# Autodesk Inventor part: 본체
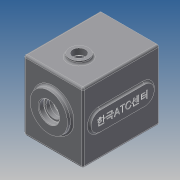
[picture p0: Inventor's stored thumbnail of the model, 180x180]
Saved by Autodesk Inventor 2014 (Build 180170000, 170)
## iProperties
Created: 2016-02
Part Number: 본체
Material: 알루미늄 6061
Document SubType Name: Modeling
Designer: mduedu
Density: 2.71 g/cm^3
Appearance: 기본값
Author: mduedu
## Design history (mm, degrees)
sketch "스케치1"
  geometry: L1 (-47, -47)-(47, -47); L2 (47, -47)-(47, 63); L3 (47, 63)-(-47, 63); L4 (-47, 63)-(-47, -47); 2 further points
  constraints: 8 end point, 2 parallel, 1 horizontal, 1 midpoint, 1 perpendicular, 1 vertical alignment
  dimensions: "d0" = 94 distance of L2.end L3.end; "d155" = 110 distance of L1.end L2.end; "d156" = 47 distance from line of L1 point (0, 0)
extrude "돌출1" new body sketch "스케치1" distance "d2" = 120; taper "d3" = 0 deg
sketch "스케치3"
  geometry: L1 (47, -47)-(-47, -47) reference; L2 (47, 63)-(47, -47) reference; L3 (-47, 63)-(47, 63) reference; L4 (-47, -47)-(-47, 63) reference; L5 (37, 53)-(37, -37); L6 (37, -37)-(-37, -37); L7 (-37, -37)-(-37, 53); L8 (-37, 53)-(37, 53); 1 further point
  constraints: 8 end point, 3 other
  dimensions: "d226" = 10 distance between parallel lines of L8 L3
extrude "돌출3" cut sketch "스케치3" distance "d11" = 110; taper "d12" = 0 deg
sketch "스케치4"
  geometry: C1 r 21 at (0, 11); 1 further point
  constraints: 1 centre point, 1 vertical alignment
  dimensions: "d13" = 21 radius of C1; "d227" = 11 distance of point (0, 0) C1.centre
extrude "돌출4" join sketch "스케치4" distance "d16" = 7; taper "d17" = 0 deg
sketch "스케치5"
  geometry: C1 r 15 at (0, -20); 1 further point
  constraints: 1 centre point, 1 vertical alignment
  dimensions: "d18" = 15 radius of C1; "d20" = 20 distance of point (0, 0) C1.centre
extrude "돌출5" join sketch "스케치5" distance "d21" = 7; taper "d22" = 0 deg
sketch "스케치6"
  geometry: C1 r 30 at (0, 11); A1 r 21 centre (0, 11) between (8.978, -7.984) and (-8.978, -7.984) reference; 1 further point
  constraints: 1 centre point, 1 coincident
  dimensions: "d228" = 60 diameter of C1
extrude "돌출6" join sketch "스케치6" distance "d25" = 7; taper "d26" = -3 deg
hole "구멍1" diameter "d29" = 35; stored, may be unused: countersink angle "d33" = 90 deg, drill point angle "d35" = 0 deg; dims "d27" = 10, "d28" = 10, "d30" = 6, "d31" = 4, "d32" = 2, "d34" = 10
hole "구멍2" diameter "d38" = 22; stored, may be unused: countersink angle "d42" = 90 deg, drill point angle "d44" = 0 deg; dims "d36" = 10, "d37" = 10, "d39" = 6, "d40" = 4, "d41" = 2, "d43" = 7
hole "구멍3" diameter "d47" = 19; stored, may be unused: countersink angle "d51" = 90 deg, drill point angle "d53" = 0 deg; dims "d45" = 10, "d46" = 10, "d48" = 6, "d49" = 4, "d50" = 2, "d52" = 1
hole "구멍4" diameter "d56" = 32; stored, may be unused: countersink angle "d60" = 90 deg, drill point angle "d62" = 0 deg; dims "d57" = 6, "d58" = 4, "d59" = 2, "d61" = 8, "d220" = 10, "d221" = 10
hole "구멍5" diameter "d65" = 25; stored, may be unused: countersink angle "d69" = 90 deg, drill point angle "d71" = 0 deg; dims "d63" = 10, "d64" = 10, "d66" = 6, "d67" = 4, "d68" = 2, "d70" = 8
fillet "모깎기2" dims "d73" = 0.3
fillet "모깎기3" dims "d74" = 2
chamfer "모따기1" distance "d75" = 1; stored, may be unused: second distance "d76" = 2, angle "d77" = 45 deg
fillet "모깎기4" dims "d78" = 3
fillet "모깎기23" dims "d240" = 1
fillet "모깎기20" dims "d229" = 3
sketch "스케치23"
  geometry: L1 (-37, 53)-(37, 53) reference; L2 (37, 53)-(37, -37) reference; L3 (37, -37)-(-37, -37) reference; L4 (-37, -37)-(-37, 53) reference; L5 (44, -47)-(-44, -47) reference; L6 (47, 60)-(47, -44) reference; L7 (-44, 63)-(44, 63) reference; L8 (-47, -44)-(-47, 60) reference; C1 r 10 at (-37, 53); C2 r 10 at (37, 53); C3 r 10 at (-37, -37); C4 r 10 at (37, -37); A1 r 3 centre (-44, -44) between (-47, -44) and (-44, -47) reference; A2 r 3 centre (44, -44) between (44, -47) and (47, -44) reference; A3 r 3 centre (44, 60) between (47, 60) and (44, 63) reference; A4 r 3 centre (-44, 60) between (-44, 63) and (-47, 60) reference; 1 further point
  constraints: 4 centre point, 4 coincident, 3 equal radius
  dimensions: "d230" = 20 diameter of C1
extrude "돌출22" join sketch "스케치23" stored distance "d235" = 10; taper "d236" = 0 deg
fillet "모깎기21" dims "d237" = 3
node "작업 평면1"
fillet "모깎기22" dims "d239" = 1
sketch "스케치12"
  geometry: A1 r 10 centre (-37, 53) between (-34.692, 43.27) and (-27.27, 50.692) reference; A2 r 10 centre (37, 53) between (27.27, 50.692) and (34.692, 43.27) reference; A3 r 10 centre (37, -37) between (34.692, -27.27) and (27.27, -34.692) reference; A4 r 10 centre (-37, -37) between (-27.27, -34.692) and (-34.692, -27.27) reference; 5 further points
  constraints: 4 coincident
hole "구멍6" sketch "스케치12" at (-37, 53), (37, 53), (37, -37), (-37, -37) diameter "d122" = 3.242; stored, may be unused: countersink angle "d126" = 90 deg, drill point angle "d128" = 120 deg; dims "d123" = 7, "d124" = 4, "d125" = 2, "d127" = 9
sketch "스케치20"
  geometry: L1 (44, 0)-(-44, 0) reference; L2 (44, -120)-(-44, -120) reference; L3 (0, 0)-(0, -120); L4 (-44, -120)-(-44, 0) reference; L5 (44, 0)-(44, -120) reference; C1 r 10 at (0, -79)
  constraints: 2 end point, 1 centre point, 1 midpoint, 1 point on line
  dimensions: "d189" = 20 diameter of C1; "d190" = 41 distance from line of C1.centre L2
extrude "돌출19" cut sketch "스케치20" stored distance "d191" = 10; taper "d192" = 0 deg
sketch "스케치18"
  geometry: C1 r 15 at (0, -79); C2 r 10 at (0, -79) reference; 1 further point
  constraints: 1 centre point, 1 concentric
  dimensions: "d174" = 30 diameter of C1
extrude "돌출17" join sketch "스케치18" distance "d175" = 5; taper "d176" = 0 deg
fillet "모깎기16" dims "d177" = 3
sketch "스케치19"
  geometry: C1 r 15 at (24.351, 79); C2 r 10 at (24.351, 79) reference; 1 further point
  constraints: 1 centre point, 1 concentric
  dimensions: "d178" = 30 diameter of C1
extrude "돌출18" cut sketch "스케치19" distance "d181" = 5; taper "d182" = 0 deg
chamfer "모따기5" distance "d183" = 1; stored, may be unused: second distance "d184" = 2, angle "d185" = 45 deg
fillet "모깎기24" dims "d242" = 3, "d243" = 3
sketch "스케치24"
  geometry: L1 (-95, 67)-(-25, 67); L2 (-25, 67)-(-25, 37); L3 (-25, 37)-(-95, 37); L4 (-95, 37)-(-95, 67); L5 (0, 0)-(0, 104) reference; L6 (-95, 52)-(-25, 52); L7 (-60, 67)-(-60, 37); A1 r 15 centre (-95, 52) between (-95, 37) and (-95, 67); A2 r 15 centre (-25, 52) between (-25, 67) and (-25, 37); A3 r 15 centre (-25, 52) between (-25, 37) and (-25, 67); A4 r 15 centre (-95, 52) between (-95, 67) and (-95, 37); 2 further points
  constraints: 12 end point, 8 point on circle, 5 midpoint, 4 centre point, 2 parallel, 2 perpendicular, 1 horizontal, 1 horizontal alignment
  dimensions: "d244" = 60 distance between parallel lines of L7 L5; "d245" = 100 dimension on A2 A1; "d246" = 30 distance between parallel lines of L3 L1
extrude "돌출23" join sketch "스케치24" distance "d247" = 3; taper "d248" = 0 deg
fillet "모깎기25" dims "d249" = 3
sketch "스케치25"
  geometry: L1 (-25, 67)-(-95, 67) reference; L2 (-95, 37)-(-25, 37) reference; A1 r 15 centre (-95, 52) between (-95, 67) and (-95, 37) reference; A2 r 15 centre (-25, 52) between (-25, 37) and (-25, 67) reference; 3 further points
  constraints: 1 horizontal alignment, 1 midpoint, 1 vertical alignment, 1 other
feature "엠보싱3" sketch "스케치25" dims "d250" = 0.5, "d251" = 0
sketch "스케치26"
  geometry: L1 (14.367, 127)-(73.633, 127) reference; L2 (0, 0)-(88, 0) reference; L3 (88, 120)-(0, 120) reference; 5 further points
  constraints: 3 vertical alignment, 2 midpoint
  dimensions: "d252" = 35 distance from line of point (44, 35) L2; "d253" = 35 distance from line of point (44, 85) L3; "d254" = 50 distance of point (44, 35) point (44, 85) (derived)
hole "구멍8" sketch "스케치26" at (44, 85), (44, 35) diameter "d255" = 6.647; stored, may be unused: countersink angle "d259" = 90 deg, drill point angle "d261" = 118 deg; dims "d256" = 6, "d257" = 4, "d258" = 2, "d260" = 8
node "솔리드1"
node "투영된 루프1"
node "투영된 루프4"
node "투영된 루프5"
node "투영된 루프6"
